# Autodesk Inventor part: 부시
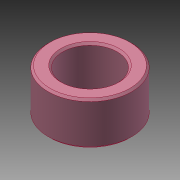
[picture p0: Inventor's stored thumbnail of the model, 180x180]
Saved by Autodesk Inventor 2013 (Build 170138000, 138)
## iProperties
Created: 2010-12
Part Number: 부시
Document SubType Name: Modeling
Designer: 진현석
Density: 1 g/cm^3
Material: 강철, 연강
Author: 진현석
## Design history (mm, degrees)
sketch "스케치1"
  geometry: C1 r 21.5 at (0, 0) reference; C2 r 31 at (0, 0) reference; C3 r 14 at (0, 0) reference; 1 further point
extrude "돌출1" new body sketch "스케치1" distance "d0" = 22; taper "d1" = 0 deg
chamfer "모따기1" distance "d2" = 1; stored, may be unused: second distance "d3" = 2, angle "d4" = 45 deg
node "솔리드1"
node "참조1"
node "참조2"
